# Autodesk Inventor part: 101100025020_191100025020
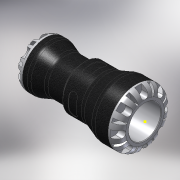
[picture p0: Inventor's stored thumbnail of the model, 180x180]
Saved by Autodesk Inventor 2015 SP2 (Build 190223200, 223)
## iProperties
Created: 2016-12
Part Number: 101100025020_191100025020
Material: PVC-Piping
Description: PLASSON REDUCING COUPLING 25X20 SERIES 1
Document SubType Name: Modeling
Designer: KIM
Mass: 108.5 g
Surface Area: 238.202 cm^2
Volume: 77.5001 cm^3
Density: 1.4 g/cm^3
Appearance: Black Cast
Author: KIM
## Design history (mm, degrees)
derived "1011.ipt"
feature "Solid1::1011.ipt"
tag "TaggingFeature1"
body "Solid1"
other parameters: "d2" = 20.16, "d3" = 25, "d4" = 47, "d6" = 48, "d7" = 2.08333, "d8" = 41, "d10" = 25, "d11" = 18.9, "d12" = 45, "d13" = 1.66667, "d14" = 37.6, "d15" = 32.8, "d16" = 20 deg, "d17" = 20 deg, "d18" = 130 deg, "d22" = 6.8, "d25" = 6.8, "d26" = 0, "d28" = 360 deg, "d30" = 8 deg, "d31" = 0.5, "d32" = 8 deg, "d33" = 0.5, "d35" = 0, "d37" = 360 deg, "d39" = 6.4, "d42" = 6.4, "d43" = 0, "d45" = 360 deg, "d47" = 0.4, "d48" = 8 deg, "d49" = 8 deg, "d50" = 0.4, "d52" = 0, "d54" = 360 deg, "d56" = 8.2, "d57" = 9.4, "d58" = 0.5, "d60" = 5.64, "d61" = 6.25, "d62" = 11.34, "d63" = 0, "d66" = 0, "d68" = 360 deg, "d75" = 7.26119, "d77" = 36.66, "d78" = 0.47, "d_" = 25, "E_" = 47, "l_" = 48, "E1" = 41, "l1" = 45, "Plasson" = 1, "d20" = 8, "d21" = 8.5, "d23" = 47, "d40" = 41, "d41" = 25, "d59" = 14.52239
